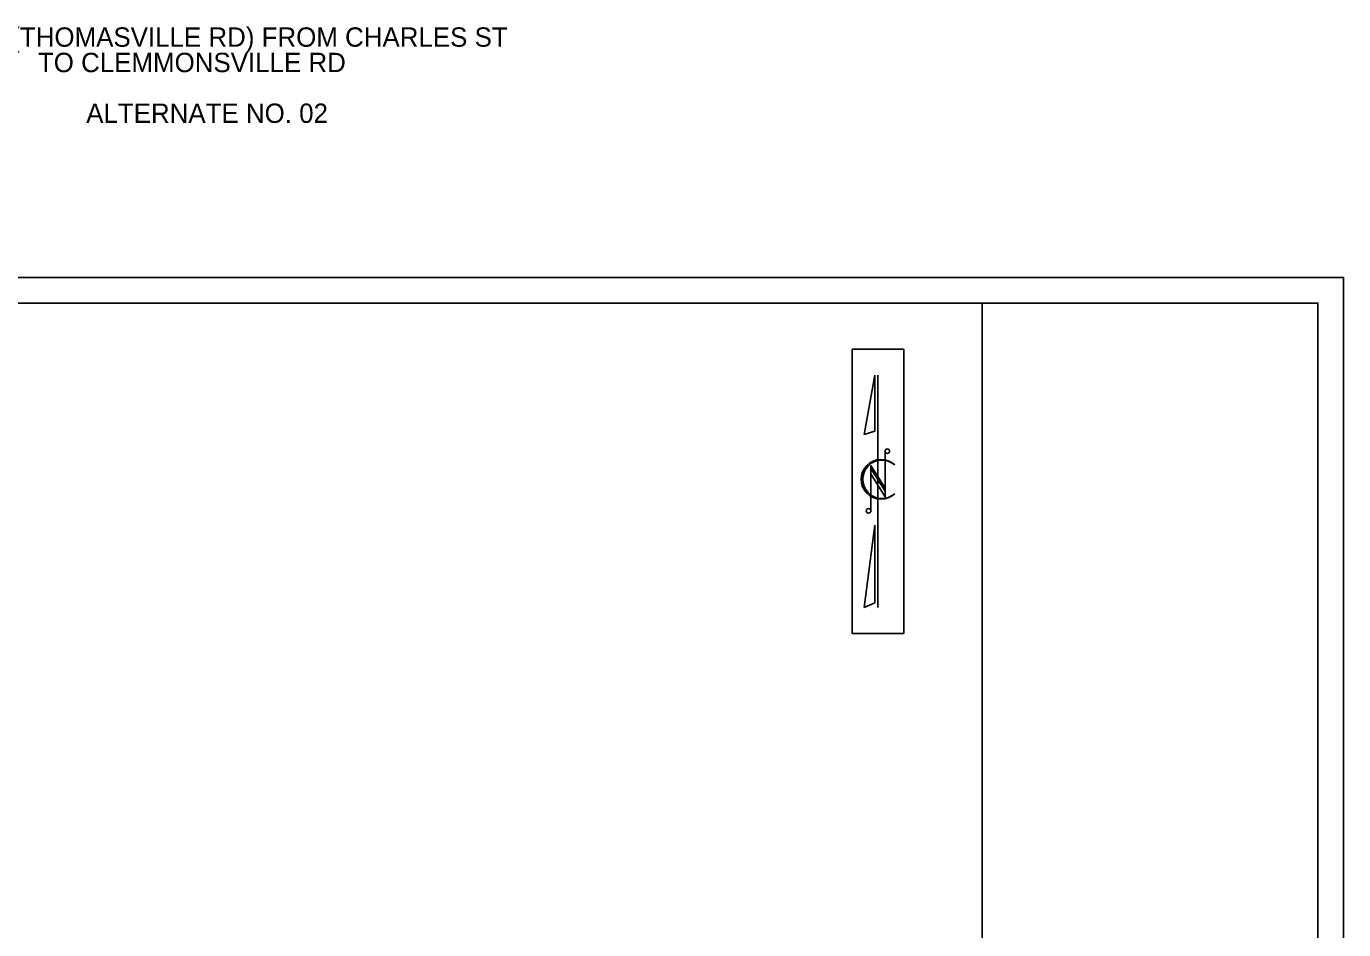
# Model space of a CAD drawing. Extents: x 1636954 to 1644154, y 841334 to 845582.
# Drawn here: x 1641603 to 1644154, y 843470 to 845220 of the extents above; entities that cross this region are included whole.
import ezdxf

# ---------------------------------------------------------------- set-up
doc = ezdxf.new("R2010")
doc.units = 0
for name, color, linetype in [('Scratch_Level_1', 7, 'Continuous'), ('Sheet North Arrow CELL', 7, 'Continuous'), ('Sheet Plan And Profile CELL', 7, 'Continuous'), ('Sheet Title CELL', 7, 'Continuous')]:
    doc.layers.add(name, color=color, linetype=linetype)

msp = doc.modelspace()

# ---------------------------------------------------------------- linework, layer by layer
at = {"layer": 'Scratch_Level_1'}
msp.add_lwpolyline([(1636954.2, 841333.9), (1636954.2, 844733.9), (1644154.2, 844733.9), (1644154.2, 841333.9)], close=True, dxfattribs=at)
at = {"layer": 'Sheet North Arrow CELL'}
for p, q in [((1643225.9, 844429.5), (1643246.4, 844544.6)), ((1643246.4, 844544.6), (1643246.4, 844436.2)), ((1643252.4, 844094.2), (1643252.4, 844544.6)), ((1643246.4, 844436.2), (1643225.9, 844429.5)), ((1643266.1, 844309.1), (1643266.1, 844397.1)), ((1643238.6, 844369.7), (1643266.1, 844325.7)), ((1643238.6, 844369.7), (1643238.6, 844281.7)), ((1643225.9, 844094.2), (1643246.4, 844254.2)), ((1643246.4, 844254.2), (1643246.4, 844103.6)), ((1643246.4, 844103.6), (1643225.9, 844094.2))]:
    msp.add_line(p, q, dxfattribs=at)
msp.add_lwpolyline([(1643238.6, 844353.1), (1643238.6, 844363.5), (1643266.1, 844319.5), (1643266.1, 844309.1)], close=True, dxfattribs=at)
for centre in [(1643270.5, 844397.1), (1643234.2, 844281.7)]:
    msp.add_circle(centre, 4.4, dxfattribs=at)
for centre, radius, start, end in [((1643258.3, 844342.7), 38.4, 46.4686, 313.5314), ((1643260.1, 844342.7), 37.2, 48.4295, 311.5705)]:
    msp.add_arc(centre, radius, start, end, dxfattribs=at)
at = {"layer": 'Sheet Plan And Profile CELL'}
for points in [[(1637004.2, 841383.9), (1637004.2, 844683.9), (1644104.2, 844683.9), (1644104.2, 841383.9)], [(1643202.4, 844044.2), (1643202.4, 844594.6), (1643302.4, 844594.6), (1643302.4, 844044.2)]]:
    msp.add_lwpolyline(points, close=True, dxfattribs=at)
msp.add_lwpolyline([(1643454.2, 844683.9), (1643454.2, 841383.9)], dxfattribs=at)

# ---------------------------------------------------------------- texts
at = {"layer": 'Sheet Title CELL'}
for s, p in [('I-5880 - NC 109 (THOMASVILLE RD) FROM CHARLES ST', (1641203.3, 845180.5)), ('TO CLEMMONSVILLE RD', (1641625.6, 845131.3)), ('ALTERNATE NO. 02', (1641719.1, 845033))]:
    msp.add_text(s, height=37.5, rotation=360, dxfattribs=at).set_placement(p)

doc.saveas('drawing.dxf')
